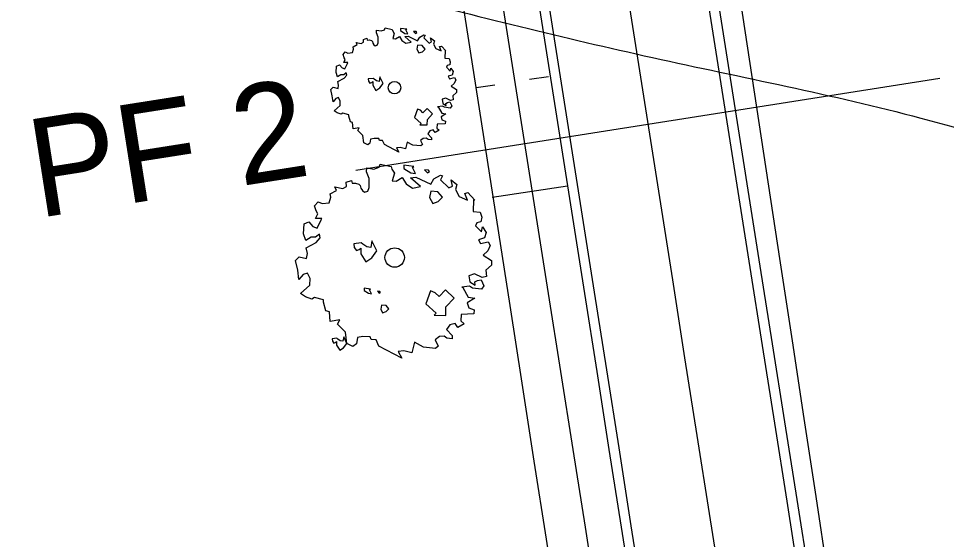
# Model space of a CAD drawing. Extents: x -477701 to -476785, y -1116511 to -1115314.
# Drawn here: x -477309.69 to -477286.15, y -1116194.17 to -1116180.95 of the extents above; entities that cross this region are included whole.
import ezdxf

# ---------------------------------------------------------------- set-up
doc = ezdxf.new("R2010")
doc.units = 0
for name, color, linetype in [('hrana_P', 7, 'Continuous'), ('hrana_R', 7, 'Continuous'), ('IP_RBK', 7, 'Continuous'), ('POLYGONY_SITUACE_PF', 7, 'Continuous'), ('POLYGONY_SITUACE_PF_POPISY', 7, 'Continuous'), ('svahování', 7, 'Continuous'), ('Vrstevnice_vedlejsi', 7, 'Continuous')]:
    doc.layers.add(name, color=color, linetype=linetype)

msp = doc.modelspace()

# ---------------------------------------------------------------- linework, layer by layer
at = {"layer": 'hrana_P'}
for points in [[(-477290.359, -1116187.146), (-477292.462, -1116173.305)], [(-477297.217, -1116188.227), (-477299.372, -1116174.394)], [(-477290.058, -1116189.123), (-477290.359, -1116187.146)], [(-477296.911, -1116190.204), (-477297.217, -1116188.227)], [(-477289.758, -1116191.101), (-477290.058, -1116189.123)], [(-477296.605, -1116192.18), (-477296.911, -1116190.204)], [(-477289.457, -1116193.078), (-477289.758, -1116191.101)], [(-477296.298, -1116194.157), (-477296.605, -1116192.18)], [(-477289.157, -1116195.055), (-477289.457, -1116193.078)], [(-477295.992, -1116196.133), (-477296.298, -1116194.157)]]:
    msp.add_lwpolyline(points, dxfattribs=at)
at = {"layer": 'hrana_R'}
for points in [[(-477291.126, -1116187.267), (-477293.307, -1116173.438)], [(-477293.06, -1116173.399), (-477290.879, -1116187.228)], [(-477295.282, -1116173.749), (-477293.102, -1116187.579)], [(-477295.078, -1116187.89), (-477297.258, -1116174.061)], [(-477296.244, -1116187.929), (-477298.424, -1116174.1)], [(-477295.325, -1116187.929), (-477297.505, -1116174.1)], [(-477290.879, -1116187.228), (-477290.568, -1116189.204)], [(-477290.815, -1116189.243), (-477291.126, -1116187.267)], [(-477293.102, -1116187.579), (-477292.791, -1116189.554)], [(-477295.932, -1116189.905), (-477296.244, -1116187.929)], [(-477295.013, -1116189.905), (-477295.325, -1116187.929)], [(-477294.766, -1116189.866), (-477295.078, -1116187.89)], [(-477290.503, -1116191.218), (-477290.815, -1116189.243)], [(-477290.568, -1116189.204), (-477290.257, -1116191.179)], [(-477292.791, -1116189.554), (-477292.479, -1116191.53)], [(-477295.621, -1116191.88), (-477295.932, -1116189.905)], [(-477294.702, -1116191.88), (-477295.013, -1116189.905)], [(-477294.455, -1116191.841), (-477294.766, -1116189.866)], [(-477290.192, -1116193.194), (-477290.503, -1116191.218)], [(-477290.257, -1116191.179), (-477289.945, -1116193.155)], [(-477292.479, -1116191.53), (-477292.168, -1116193.505)], [(-477295.309, -1116193.856), (-477295.621, -1116191.88)], [(-477294.39, -1116193.856), (-477294.702, -1116191.88)], [(-477294.143, -1116193.817), (-477294.455, -1116191.841)], [(-477289.881, -1116195.169), (-477290.192, -1116193.194)], [(-477289.945, -1116193.155), (-477289.634, -1116195.131)], [(-477292.168, -1116193.505), (-477291.856, -1116195.481)], [(-477293.832, -1116195.792), (-477294.143, -1116193.817)], [(-477294.998, -1116195.831), (-477295.309, -1116193.856)], [(-477294.079, -1116195.831), (-477294.39, -1116193.856)]]:
    msp.add_lwpolyline(points, dxfattribs=at)
at = {"layer": 'IP_RBK'}
for points in [[(-477299.233, -1116181.442), (-477299.137, -1116181.515), (-477299.16, -1116181.597), (-477299.101, -1116181.71), (-477298.967, -1116181.772), (-477299.009, -1116181.662), (-477298.959, -1116181.647), (-477298.844, -1116181.771), (-477298.867, -1116181.763), (-477298.875, -1116181.953), (-477298.759, -1116181.966), (-477298.734, -1116182.049), (-477298.748, -1116182.125), (-477298.815, -1116182.141), (-477298.834, -1116182.186), (-477298.737, -1116182.284), (-477298.723, -1116182.205), (-477298.664, -1116182.296), (-477298.687, -1116182.382), (-477298.785, -1116182.414), (-477298.755, -1116182.475), (-477298.631, -1116182.448), (-477298.597, -1116182.508), (-477298.634, -1116182.595), (-477298.71, -1116182.668), (-477298.573, -1116182.75), (-477298.576, -1116182.829), (-477298.667, -1116182.912), (-477298.658, -1116183.011), (-477298.727, -1116183.027), (-477298.849, -1116182.968), (-477298.942, -1116182.999), (-477298.926, -1116183.101), (-477298.839, -1116183.155), (-477298.846, -1116183.101), (-477298.802, -1116183.077), (-477298.744, -1116183.065), (-477298.698, -1116183.164), (-477298.74, -1116183.221), (-477298.884, -1116183.201), (-477298.934, -1116183.169), (-477299.057, -1116183.186), (-477299.044, -1116183.191), (-477298.953, -1116183.351), (-477298.849, -1116183.365), (-477298.969, -1116183.443), (-477298.945, -1116183.521), (-477298.86, -1116183.557), (-477298.862, -1116183.619), (-477299.071, -1116183.63), (-477299.075, -1116183.732), (-477299.017, -1116183.782), (-477299.122, -1116183.842), (-477299.165, -1116183.777), (-477299.253, -1116183.798), (-477299.305, -1116183.877), (-477299.214, -1116183.972), (-477299.213, -1116184.028), (-477299.3, -1116184.015), (-477299.345, -1116183.985), (-477299.423, -1116183.989), (-477299.491, -1116184.042), (-477299.442, -1116184.144), (-477299.484, -1116184.182), (-477299.683, -1116184.161), (-477299.83, -1116184.083), (-477299.868, -1116184.257), (-477300.002, -1116184.221), (-477300.096, -1116184.232), (-477300.036, -1116184.34), (-477300.406, -1116184.148), (-477300.451, -1116184.044), (-477300.533, -1116184.04), (-477300.551, -1116183.992), (-477300.667, -1116183.99), (-477300.755, -1116184.007), (-477300.774, -1116184.107), (-477300.83, -1116184.152), (-477300.929, -1116184.101), (-477300.95, -1116183.919), (-477301.083, -1116183.79), (-477301.045, -1116183.718), (-477301.202, -1116183.746), (-477301.212, -1116183.59), (-477301.269, -1116183.572), (-477301.309, -1116183.428), (-477301.309, -1116183.394), (-477301.457, -1116183.354), (-477301.5, -1116183.379), (-477301.601, -1116183.341), (-477301.682, -1116183.29), (-477301.531, -1116183.155), (-477301.526, -1116183.048), (-477301.57, -1116182.956), (-477301.64, -1116182.979), (-477301.708, -1116183.061), (-477301.728, -1116182.908), (-477301.766, -1116182.749), (-477301.704, -1116182.694), (-477301.583, -1116182.72), (-477301.571, -1116182.641), (-477301.591, -1116182.544), (-477301.426, -1116182.458), (-477301.363, -1116182.385), (-477301.375, -1116182.325), (-477301.437, -1116182.374), (-477301.51, -1116182.374), (-477301.597, -1116182.428), (-477301.632, -1116182.316), (-477301.622, -1116182.154), (-477301.545, -1116182.123), (-477301.479, -1116182.2), (-477301.409, -1116182.226), (-477301.344, -1116182.091), (-477301.337, -1116182.068), (-477301.437, -1116182.067), (-477301.399, -1116181.991), (-477301.428, -1116181.944), (-477301.455, -1116181.861), (-477301.398, -1116181.795), (-477301.331, -1116181.824), (-477301.217, -1116181.813), (-477301.188, -1116181.724), (-477301.2, -1116181.669), (-477301.098, -1116181.612), (-477301.125, -1116181.553), (-477300.993, -1116181.58), (-477300.934, -1116181.547), (-477300.937, -1116181.48), (-477300.851, -1116181.451), (-477300.842, -1116181.496), (-477300.79, -1116181.492), (-477300.733, -1116181.509), (-477300.712, -1116181.533), (-477300.702, -1116181.576), (-477300.675, -1116181.614), (-477300.64, -1116181.641), (-477300.587, -1116181.626), (-477300.563, -1116181.562), (-477300.563, -1116181.42), (-477300.61, -1116181.311), (-477300.604, -1116181.244), (-477300.487, -1116181.264), (-477300.404, -1116181.235), (-477300.384, -1116181.185), (-477300.209, -1116181.224), (-477300.195, -1116181.268), (-477300.155, -1116181.329), (-477300.191, -1116181.456), (-477300.127, -1116181.461), (-477300.027, -1116181.404), (-477299.965, -1116181.506), (-477299.859, -1116181.576), (-477299.729, -1116181.549), (-477299.892, -1116181.405), (-477299.805, -1116181.398), (-477299.563, -1116181.511), (-477299.51, -1116181.425), (-477299.402, -1116181.361), (-477299.373, -1116181.374), (-477299.404, -1116181.44), (-477299.271, -1116181.571), (-477299.209, -1116181.543)], [(-477300.001, -1116181.255), (-477299.888, -1116181.327), (-477299.814, -1116181.336), (-477299.861, -1116181.237), (-477299.841, -1116181.222), (-477300, -1116181.199)], [(-477299.665, -1116181.276), (-477299.616, -1116181.327), (-477299.585, -1116181.302), (-477299.6, -1116181.28)], [(-477299.564, -1116181.627), (-477299.581, -1116181.727), (-477299.532, -1116181.823), (-477299.443, -1116181.79), (-477299.373, -1116181.724), (-477299.446, -1116181.636)], [(-477300.703, -1116182.55), (-477300.703, -1116182.642), (-477300.62, -1116182.771), (-477300.523, -1116182.709), (-477300.441, -1116182.597), (-477300.52, -1116182.43), (-477300.539, -1116182.543), (-477300.605, -1116182.532), (-477300.667, -1116182.487), (-477300.693, -1116182.467), (-477300.814, -1116182.482), (-477300.807, -1116182.542), (-477300.774, -1116182.591), (-477300.728, -1116182.572)], [(-477299.569, -1116183.246), (-477299.642, -1116183.456), (-477299.474, -1116183.61), (-477299.506, -1116183.644), (-477299.32, -1116183.649), (-477299.317, -1116183.508), (-477299.183, -1116183.366), (-477299.325, -1116183.232), (-477299.427, -1116183.34), (-477299.494, -1116183.278)], [(-477298.715, -1116185.045), (-477298.566, -1116185.158), (-477298.601, -1116185.287), (-477298.51, -1116185.463), (-477298.3, -1116185.559), (-477298.367, -1116185.388), (-477298.288, -1116185.364), (-477298.109, -1116185.558), (-477298.144, -1116185.546), (-477298.158, -1116185.842), (-477297.976, -1116185.863), (-477297.937, -1116185.992), (-477297.96, -1116186.11), (-477298.064, -1116186.135), (-477298.093, -1116186.205), (-477297.942, -1116186.358), (-477297.921, -1116186.234), (-477297.828, -1116186.377), (-477297.864, -1116186.511), (-477298.017, -1116186.561), (-477297.97, -1116186.655), (-477297.777, -1116186.613), (-477297.723, -1116186.707), (-477297.782, -1116186.843), (-477297.899, -1116186.957), (-477297.687, -1116187.085), (-477297.691, -1116187.207), (-477297.833, -1116187.337), (-477297.818, -1116187.492), (-477297.926, -1116187.516), (-477298.117, -1116187.425), (-477298.261, -1116187.473), (-477298.236, -1116187.632), (-477298.1, -1116187.716), (-477298.111, -1116187.632), (-477298.043, -1116187.595), (-477297.953, -1116187.576), (-477297.881, -1116187.729), (-477297.946, -1116187.818), (-477298.171, -1116187.788), (-477298.249, -1116187.738), (-477298.44, -1116187.765), (-477298.42, -1116187.773), (-477298.279, -1116188.022), (-477298.116, -1116188.043), (-477298.304, -1116188.166), (-477298.267, -1116188.286), (-477298.133, -1116188.343), (-477298.136, -1116188.44), (-477298.462, -1116188.457), (-477298.469, -1116188.616), (-477298.379, -1116188.694), (-477298.542, -1116188.787), (-477298.61, -1116188.686), (-477298.747, -1116188.718), (-477298.828, -1116188.842), (-477298.686, -1116188.989), (-477298.685, -1116189.077), (-477298.82, -1116189.056), (-477298.89, -1116189.01), (-477299.011, -1116189.016), (-477299.118, -1116189.099), (-477299.042, -1116189.258), (-477299.107, -1116189.318), (-477299.417, -1116189.285), (-477299.646, -1116189.163), (-477299.706, -1116189.434), (-477299.914, -1116189.378), (-477300.06, -1116189.395), (-477299.967, -1116189.563), (-477300.544, -1116189.264), (-477300.614, -1116189.102), (-477300.743, -1116189.096), (-477300.771, -1116189.021), (-477300.951, -1116189.018), (-477301.089, -1116189.044), (-477301.118, -1116189.201), (-477301.205, -1116189.271), (-477301.36, -1116189.191), (-477301.392, -1116188.907), (-477301.6, -1116188.706), (-477301.54, -1116188.594), (-477301.785, -1116188.638), (-477301.801, -1116188.394), (-477301.89, -1116188.366), (-477301.953, -1116188.142), (-477301.952, -1116188.089), (-477302.183, -1116188.026), (-477302.249, -1116188.065), (-477302.408, -1116188.006), (-477302.534, -1116187.926), (-477302.298, -1116187.716), (-477302.291, -1116187.549), (-477302.359, -1116187.407), (-477302.468, -1116187.442), (-477302.575, -1116187.569), (-477302.606, -1116187.33), (-477302.665, -1116187.084), (-477302.568, -1116186.997), (-477302.379, -1116187.038), (-477302.36, -1116186.914), (-477302.392, -1116186.763), (-477302.135, -1116186.63), (-477302.037, -1116186.516), (-477302.054, -1116186.421), (-477302.152, -1116186.499), (-477302.266, -1116186.498), (-477302.401, -1116186.583), (-477302.455, -1116186.408), (-477302.44, -1116186.156), (-477302.32, -1116186.107), (-477302.218, -1116186.228), (-477302.109, -1116186.268), (-477302.006, -1116186.057), (-477301.996, -1116186.022), (-477302.151, -1116186.019), (-477302.093, -1116185.902), (-477302.137, -1116185.828), (-477302.18, -1116185.698), (-477302.09, -1116185.596), (-477301.987, -1116185.64), (-477301.809, -1116185.623), (-477301.764, -1116185.485), (-477301.782, -1116185.399), (-477301.624, -1116185.311), (-477301.665, -1116185.218), (-477301.46, -1116185.261), (-477301.368, -1116185.209), (-477301.373, -1116185.104), (-477301.238, -1116185.059), (-477301.224, -1116185.13), (-477301.142, -1116185.123), (-477301.055, -1116185.149), (-477301.021, -1116185.188), (-477301.006, -1116185.254), (-477300.963, -1116185.314), (-477300.909, -1116185.355), (-477300.826, -1116185.331), (-477300.79, -1116185.232), (-477300.789, -1116185.011), (-477300.862, -1116184.841), (-477300.853, -1116184.737), (-477300.671, -1116184.767), (-477300.541, -1116184.723), (-477300.51, -1116184.645), (-477300.238, -1116184.706), (-477300.215, -1116184.774), (-477300.153, -1116184.869), (-477300.208, -1116185.066), (-477300.11, -1116185.074), (-477299.954, -1116184.986), (-477299.856, -1116185.145), (-477299.691, -1116185.254), (-477299.488, -1116185.211), (-477299.743, -1116184.988), (-477299.607, -1116184.976), (-477299.23, -1116185.153), (-477299.148, -1116185.019), (-477298.979, -1116184.919), (-477298.934, -1116184.939), (-477298.982, -1116185.042), (-477298.774, -1116185.246), (-477298.678, -1116185.202)], [(-477299.913, -1116184.753), (-477299.736, -1116184.866), (-477299.621, -1116184.881), (-477299.695, -1116184.726), (-477299.663, -1116184.702), (-477299.911, -1116184.667)], [(-477299.388, -1116184.787), (-477299.312, -1116184.866), (-477299.264, -1116184.828), (-477299.288, -1116184.793)], [(-477299.232, -1116185.333), (-477299.258, -1116185.49), (-477299.181, -1116185.64), (-477299.043, -1116185.589), (-477298.933, -1116185.484), (-477299.047, -1116185.348)], [(-477301.007, -1116186.774), (-477301.007, -1116186.916), (-477300.878, -1116187.118), (-477300.727, -1116187.021), (-477300.599, -1116186.846), (-477300.722, -1116186.586), (-477300.752, -1116186.762), (-477300.855, -1116186.744), (-477300.951, -1116186.674), (-477300.992, -1116186.644), (-477301.18, -1116186.667), (-477301.169, -1116186.761), (-477301.118, -1116186.837), (-477301.046, -1116186.807)], [(-477300.92, -1116187.849), (-477300.806, -1116187.921), (-477300.733, -1116187.93), (-477300.78, -1116187.831), (-477300.76, -1116187.816), (-477300.918, -1116187.793)], [(-477300.583, -1116187.87), (-477300.535, -1116187.921), (-477300.504, -1116187.896), (-477300.519, -1116187.874)], [(-477299.239, -1116187.857), (-477299.352, -1116188.185), (-477299.092, -1116188.426), (-477299.141, -1116188.479), (-477298.851, -1116188.486), (-477298.846, -1116188.266), (-477298.637, -1116188.045), (-477298.859, -1116187.836), (-477299.018, -1116188.005), (-477299.122, -1116187.907)], [(-477300.483, -1116188.221), (-477300.5, -1116188.321), (-477300.451, -1116188.417), (-477300.362, -1116188.384), (-477300.292, -1116188.318), (-477300.364, -1116188.23)], [(-477301.622, -1116189.144), (-477301.622, -1116189.236), (-477301.539, -1116189.365), (-477301.442, -1116189.303), (-477301.36, -1116189.191), (-477301.439, -1116189.024), (-477301.458, -1116189.137), (-477301.524, -1116189.126), (-477301.586, -1116189.081), (-477301.612, -1116189.061), (-477301.733, -1116189.076), (-477301.725, -1116189.136), (-477301.693, -1116189.185), (-477301.647, -1116189.166)]]:
    msp.add_lwpolyline(points, close=True, dxfattribs=at)
for centre, radius in [((-477300.15, -1116182.704), 0.158), ((-477300.145, -1116187.013), 0.247)]:
    msp.add_circle(centre, radius, dxfattribs=at)
at = {"layer": 'POLYGONY_SITUACE_PF'}
msp.add_lwpolyline([(-477301.133, -1116184.795), (-477293.725, -1116183.627), (-477286.316, -1116182.459)], dxfattribs=at)
at = {"layer": 'svahování'}
for points in [[(-477296.246, -1116182.426), (-477296.723, -1116182.498)], [(-477296.246, -1116182.426), (-477296.723, -1116182.498)], [(-477296.246, -1116182.426), (-477296.723, -1116182.498)], [(-477298.08, -1116182.7), (-477297.602, -1116182.627)], [(-477298.08, -1116182.7), (-477297.602, -1116182.627)], [(-477298.08, -1116182.7), (-477297.602, -1116182.627)], [(-477295.76, -1116185.198), (-477297.67, -1116185.487)], [(-477295.76, -1116185.198), (-477297.67, -1116185.487)], [(-477295.76, -1116185.198), (-477297.67, -1116185.487)]]:
    msp.add_lwpolyline(points, dxfattribs=at)
at = {"layer": 'Vrstevnice_vedlejsi'}
for points in [[(-477199.82, -1116204.007), (-477200.739, -1116202.514), (-477201.27, -1116201.82), (-477201.875, -1116201.179), (-477202.552, -1116200.589), (-477207.089, -1116196.656), (-477215.486, -1116189.38), (-477227.743, -1116178.759), (-477238.175, -1116170.775), (-477246.781, -1116165.426), (-477253.562, -1116162.713), (-477260.267, -1116160.417), (-477266.895, -1116158.537), (-477273.448, -1116157.075), (-477281.2, -1116155.527), (-477290.151, -1116153.893), (-477300.303, -1116152.173), (-477308.131, -1116150.906), (-477313.636, -1116150.091), (-477316.818, -1116149.728), (-477320.571, -1116149.036), (-477324.896, -1116148.014), (-477329.793, -1116146.662), (-477335.87, -1116145.7), (-477343.126, -1116145.128), (-477351.563, -1116144.945), (-477360.546, -1116145.429), (-477370.073, -1116146.581), (-477380.147, -1116148.401), (-477387.949, -1116149.722), (-477393.48, -1116150.545), (-477396.74, -1116150.87), (-477399.688, -1116151.291), (-477402.323, -1116151.808), (-477404.646, -1116152.421), (-477408.076, -1116153.604), (-477412.612, -1116155.356), (-477418.255, -1116157.678), (-477423.245, -1116160.053), (-477427.583, -1116162.482), (-477431.268, -1116164.964), (-477433.964, -1116166.824), (-477435.672, -1116168.061), (-477436.392, -1116168.675), (-477437.552, -1116170.019), (-477439.151, -1116172.092), (-477441.189, -1116174.894), (-477442.91, -1116177.326), (-477444.315, -1116179.388), (-477445.403, -1116181.079), (-477446.061, -1116182.396), (-477446.29, -1116183.339), (-477446.09, -1116183.907), (-477445.933, -1116184.419), (-477445.817, -1116184.875), (-477445.745, -1116185.274), (-477445.711, -1116185.587), (-477445.716, -1116185.814), (-477445.759, -1116185.955), (-477446.027, -1116186.053), (-477446.522, -1116186.11), (-477447.242, -1116186.125), (-477448.164, -1116186.21), (-477449.287, -1116186.365), (-477450.611, -1116186.591), (-477451.625, -1116186.841), (-477452.328, -1116187.116), (-477452.721, -1116187.414), (-477453.447, -1116187.653), (-477454.505, -1116187.832), (-477455.895, -1116187.952), (-477457.34, -1116187.983), (-477458.839, -1116187.924), (-477460.392, -1116187.776), (-477461.247, -1116187.707)], [(-477453.209, -1116210.761), (-477447.63, -1116207.098), (-477441.8, -1116203.305), (-477437.77, -1116200.726), (-477435.54, -1116199.361), (-477434.308, -1116198.427), (-477434.076, -1116197.924), (-477434.186, -1116197.871), (-477434.417, -1116197.911), (-477434.843, -1116197.852), (-477435.029, -1116197.283), (-477434.636, -1116196.216), (-477433.662, -1116194.651), (-477432.521, -1116193.659), (-477431.212, -1116193.239), (-477429.735, -1116193.391), (-477428.556, -1116193.508), (-477427.673, -1116193.591), (-477427.087, -1116193.639), (-477425.968, -1116193.654), (-477424.314, -1116193.634), (-477422.127, -1116193.581), (-477419.527, -1116193.525), (-477416.512, -1116193.466), (-477413.083, -1116193.404), (-477410.774, -1116193.339), (-477409.583, -1116193.271), (-477409.511, -1116193.2), (-477409.092, -1116193.047), (-477408.325, -1116192.812), (-477407.212, -1116192.496), (-477406.453, -1116192.207), (-477406.047, -1116191.946), (-477405.996, -1116191.711), (-477405.956, -1116191.405), (-477405.927, -1116191.029), (-477405.91, -1116190.583), (-477405.886, -1116190.269), (-477405.856, -1116190.088), (-477405.819, -1116190.039), (-477404.813, -1116189.277), (-477402.837, -1116187.801), (-477399.893, -1116185.612), (-477397.343, -1116184.037), (-477395.187, -1116183.076), (-477393.427, -1116182.73), (-477390.441, -1116182.062), (-477386.229, -1116181.071), (-477380.792, -1116179.759), (-477376.39, -1116178.596), (-477373.023, -1116177.582), (-477370.692, -1116176.717), (-477368.571, -1116175.951), (-477366.661, -1116175.284), (-477364.961, -1116174.716), (-477363.59, -1116174.267), (-477362.55, -1116173.939), (-477361.839, -1116173.732), (-477360.359, -1116173.594), (-477358.11, -1116173.527), (-477355.092, -1116173.529), (-477350.007, -1116173.611), (-477342.855, -1116173.772), (-477333.637, -1116174.013), (-477327.001, -1116174.258), (-477322.946, -1116174.507), (-477321.473, -1116174.76), (-477318.314, -1116175.527), (-477313.468, -1116176.809), (-477306.935, -1116178.606), (-477300.313, -1116180.316), (-477293.602, -1116181.939), (-477286.801, -1116183.474), (-477278.779, -1116186.164), (-477269.536, -1116190.007), (-477259.071, -1116195.003), (-477251.273, -1116198.758), (-477246.141, -1116201.269)]]:
    msp.add_spline(points, degree=3, dxfattribs=at)

# ---------------------------------------------------------------- texts
at = {"layer": 'POLYGONY_SITUACE_PF_POPISY'}
msp.add_text('PF 2', height=2.5, rotation=8.9589, dxfattribs=at).set_placement((-477309.196, -1116186.013))

doc.saveas('drawing.dxf')
